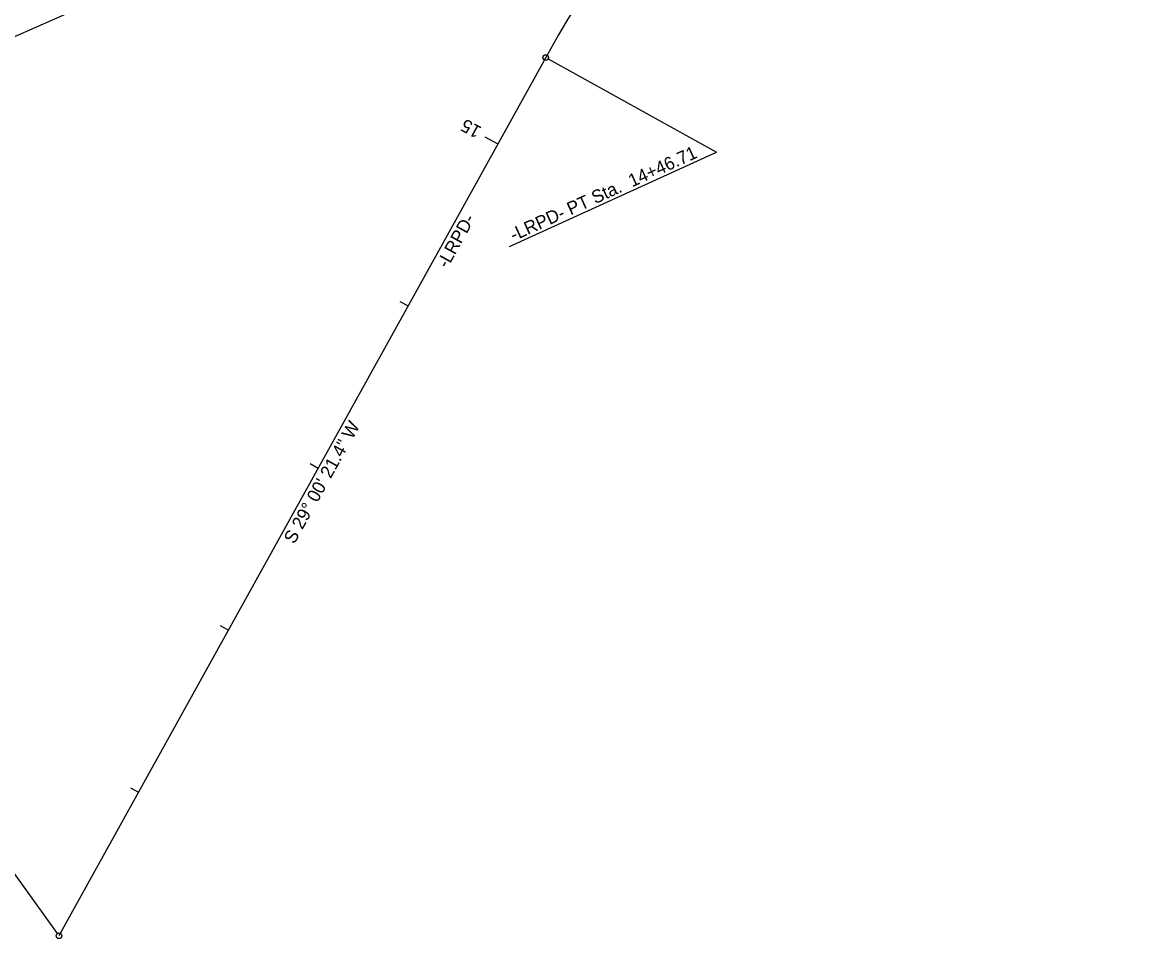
# Model space of a CAD drawing. Extents: x 2242984 to 2250974, y 661492 to 664681.
# Drawn here: x 2247792 to 2248397, y 662296 to 662790 of the extents above; entities that cross this region are included whole.
import ezdxf

# ---------------------------------------------------------------- set-up
doc = ezdxf.new("R2010")
doc.units = 0
for name, color, linetype in [('Prop Horizontal Alignment', 7, 'Continuous'), ('Prop Horizontal Alignment Curve and Spiral Data', 7, 'Continuous'), ('Prop Horizontal Alignment Direction Label', 7, 'Continuous'), ('Prop Horizontal Alignment Station Label', 7, 'Continuous'), ('Prop Horizontal Alignment Tick Label', 7, 'Continuous'), ('Prop Horizontal Alignment Tick Large', 7, 'Continuous'), ('Prop Horizontal Alignment Tick Small', 7, 'Continuous'), ('Prop Paved Shoulder', 7, 'Continuous'), ('Scratch_Level_2', 7, 'Continuous')]:
    doc.layers.add(name, color=color, linetype=linetype)

msp = doc.modelspace()

# ---------------------------------------------------------------- linework, layer by layer
at = {"layer": 'Prop Horizontal Alignment'}
msp.add_line((2248074.22, 662771.35), (2247811.46, 662297.42), dxfattribs=at)
msp.add_arc((2248686.42, 662431.92), 700, 114.43013, 150.99406, dxfattribs=at)
at = {"layer": 'Prop Horizontal Alignment Station Label'}
for p, q in [((2248075.54, 662770.62), (2248166.39, 662720.25)), ((2248054.65, 662669.33), (2248166.39, 662720.25)), ((2247810.58, 662298.64), (2247722.8, 662421.16))]:
    msp.add_line(p, q, dxfattribs=at)
for centre in [(2248074.22, 662771.35), (2247811.46, 662297.42)]:
    msp.add_circle(centre, 1.5, dxfattribs=at)
at = {"layer": 'Prop Horizontal Alignment Tick Large'}
msp.add_line((2248041.39, 662728.62), (2248048.39, 662724.75), dxfattribs=at)
at = {"layer": 'Prop Horizontal Alignment Tick Small'}
for p, q in [((2247995.52, 662639.71), (2247999.9, 662637.29)), ((2247947.03, 662552.26), (2247951.41, 662549.83)), ((2247898.54, 662464.8), (2247902.92, 662462.37)), ((2247850.05, 662377.34), (2247854.43, 662374.92))]:
    msp.add_line(p, q, dxfattribs=at)
at = {"layer": 'Prop Paved Shoulder'}
msp.add_lwpolyline([(2247748.12, 662765.04), (2247749.91, 662765.84), (2247788.02, 662782.85), (2247819.89, 662797), (2247858.38, 662814.46), (2247890.52, 662828.54), (2247929.75, 662846.07), (2247965.79, 662862.18), (2248016.34, 662884.69), (2248053.87, 662901.09), (2248085.69, 662916.48), (2248123.17, 662934.34), (2248153.89, 662949.09), (2248186.42, 662964.72), (2248216.92, 662976.74)], dxfattribs=at)
at = {"layer": 'Scratch_Level_2'}
msp.add_lwpolyline([(2247748.12, 662765.04), (2247749.91, 662765.84), (2247788.02, 662782.85), (2247819.89, 662797), (2247858.38, 662814.46), (2247890.52, 662828.54), (2247929.75, 662846.07), (2247965.79, 662862.18), (2248016.34, 662884.69), (2248053.87, 662901.09), (2248085.69, 662916.48), (2248123.17, 662934.34), (2248153.89, 662949.09), (2248186.42, 662964.72), (2248216.92, 662976.74)], dxfattribs=at)

# ---------------------------------------------------------------- texts
at = {"layer": 'Prop Horizontal Alignment Curve and Spiral Data'}
msp.add_text('-LRPD-', height=7, rotation=60.99406, dxfattribs=at).set_placement((2248021.13, 662657.21))
at = {"layer": 'Prop Horizontal Alignment Direction Label'}
msp.add_text('S 29%%d 00\' 21.4" W', height=7, rotation=60.99406, dxfattribs=at).set_placement((2247938.52, 662508.48))
at = {"layer": 'Prop Horizontal Alignment Station Label'}
msp.add_text('-LRPD- PT Sta.  14+46.71', height=7, rotation=24.49794, dxfattribs=at).set_placement((2248056.89, 662672.13))
at = {"layer": 'Prop Horizontal Alignment Tick Label'}
msp.add_text('15', height=7, rotation=150.99406, dxfattribs=at).set_placement((2248040.03, 662733.5))

doc.saveas('drawing.dxf')
